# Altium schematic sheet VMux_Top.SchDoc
size A4; DocumentNumber: 1; SheetNumber: 1; SheetTotal: 5
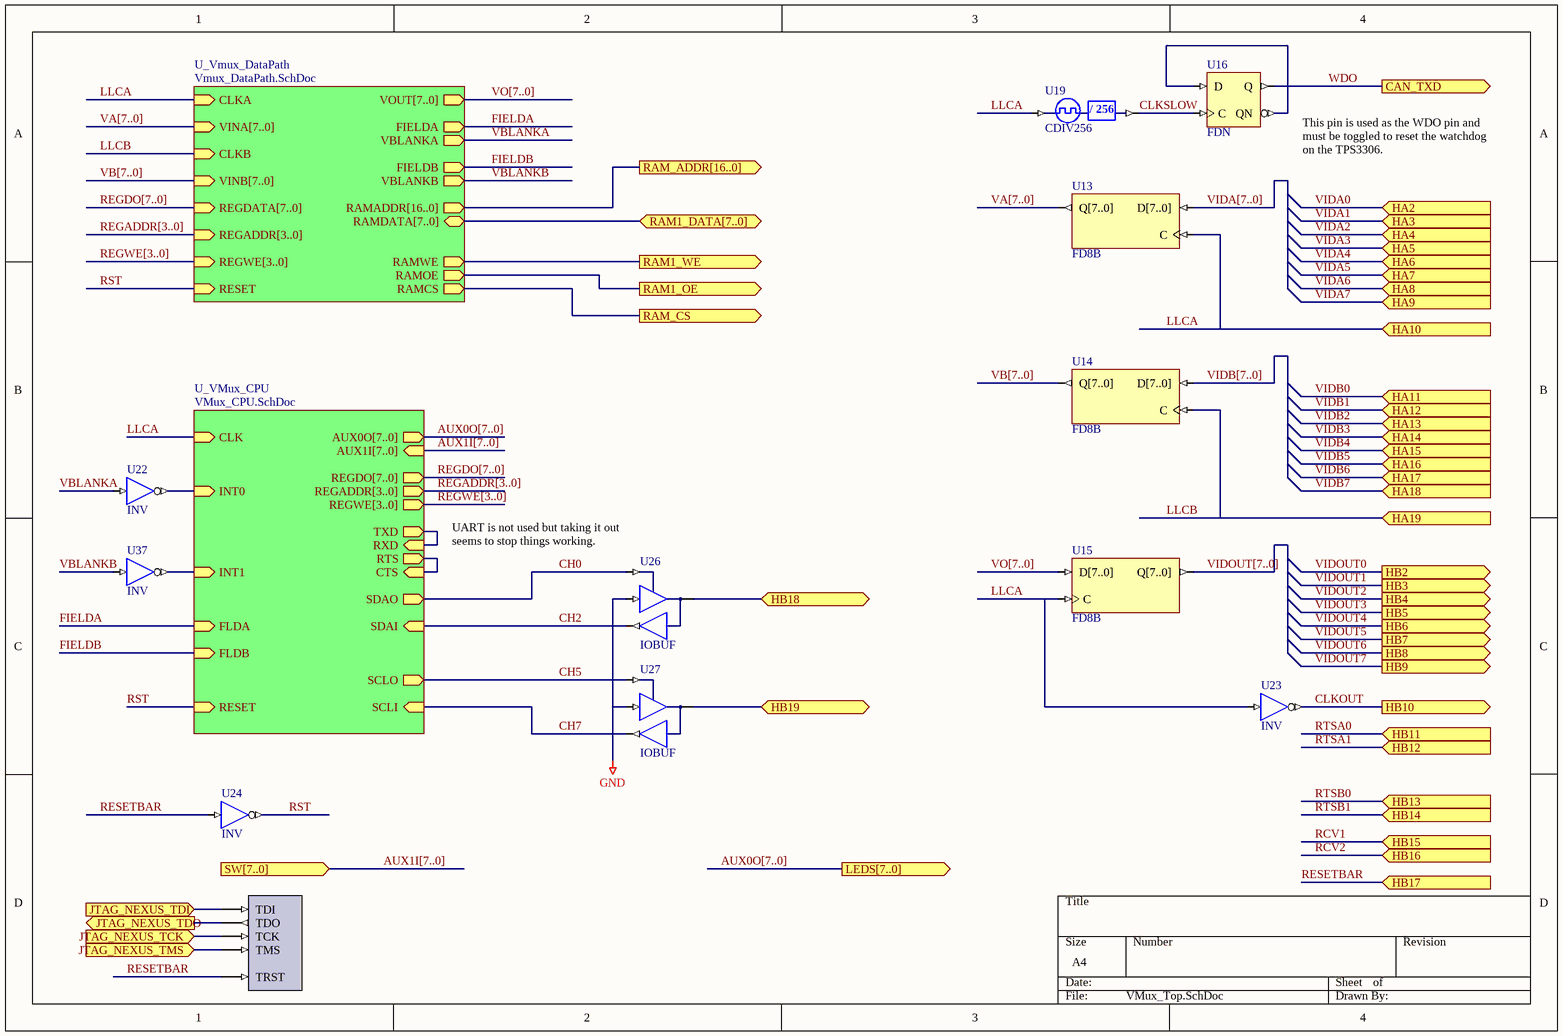
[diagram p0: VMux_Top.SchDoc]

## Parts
NEXUS_JTAG_PORT  NEXUS_JTAG_PORT  (value not drawn)
U13  FD8B
U14  FD8B
U15  FD8B
U16  FDN
U19  CDIV256
U22  INV
U23  INV
U24  INV
U26  IOBUF
U27  IOBUF
U37  INV

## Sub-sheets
U_VMux_CPU = VMux_CPU.SchDoc: CLK (in), RESET (in), SDAO (out), SCLO (out), SDAI (in), SCLI (in), AUX0O[7..0] (out), AUX1I[7..0] (in), RTS (out), TXD (out), CTS (in), RXD (in), REGDO[7..0] (out), REGADDR[3..0] (out), REGWE[3..0] (out), INT0 (in), INT1 (in), FLDA (in), FLDB (in)
U_Vmux_DataPath = Vmux_DataPath.SchDoc: REGADDR[3..0] (in), REGWE[3..0] (in), REGDATA[7..0] (in), VINA[7..0] (in), VINB[7..0] (in), CLKA (in), CLKB (in), RAMADDR[16..0] (out), RAMDATA[7..0] (bidir), RAMCS (out), RAMOE (out), RAMWE (out), VOUT[7..0] (out), RESET (in), VBLANKA (out), VBLANKB (out), FIELDA (out), FIELDB (out)

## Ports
CAN_TXD (out), HA2 (in), HA3 (in), HA4 (in), HA5 (in), HA6 (in), HA7 (in), HA8 (in), HA9 (in), HA10 (in), HA11 (in), HA12 (in), HA13 (in), HA14 (in), HA15 (in), HA16 (in), HA17 (in), HA18 (in), HA19 (in), HB2 (out), HB3 (out), HB4 (out), HB5 (out), HB6 (out), HB7 (out), HB8 (out), HB9 (out), HB10 (out), HB11 (in), HB12 (in), HB13 (in), HB14 (in), HB15 (in), HB16 (in), HB17 (in), HB18 (bidir), HB19 (bidir), JTAG_NEXUS_TCK (in), JTAG_NEXUS_TDI (in), JTAG_NEXUS_TDO (out), JTAG_NEXUS_TMS (in), LEDS[7..0] (out), RAM1_DATA[7..0] (bidir), RAM1_OE (out), RAM1_WE (out), RAM_ADDR[16..0] (out), RAM_CS (out), SW[7..0] (in)

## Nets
GND: U26.I U27.I
CH0: U26.T ; sheet U_VMux_CPU/SDAO
CH2: U26.O ; sheet U_VMux_CPU/SDAI
CH5: U27.T ; sheet U_VMux_CPU/SCLO
CH7: U27.O ; sheet U_VMux_CPU/SCLI
CLKOUT: U23.O ; port HB10
CLKSLOW: U16.C U19.CLKDV
FIELDA: sheet U_VMux_CPU/FLDA, sheet U_Vmux_DataPath/FIELDA
FIELDB: sheet U_VMux_CPU/FLDB, sheet U_Vmux_DataPath/FIELDB
HB18: U26.IO ; port HB18
HB19: U27.IO ; port HB19
JTAG_NEXUS_TCK: NEXUS_JTAG_PORT.TCK ; port JTAG_NEXUS_TCK
JTAG_NEXUS_TDI: NEXUS_JTAG_PORT.TDI ; port JTAG_NEXUS_TDI
JTAG_NEXUS_TDO: NEXUS_JTAG_PORT.TDO ; port JTAG_NEXUS_TDO
JTAG_NEXUS_TMS: NEXUS_JTAG_PORT.TMS ; port JTAG_NEXUS_TMS
LLCA: U13.C U15.C U19.CLKIN U23.I ; port HA10, sheet U_VMux_CPU/CLK, sheet U_Vmux_DataPath/CLKA
LLCB: U14.C ; port HA19, sheet U_Vmux_DataPath/CLKB
RAM1_OE: port RAM1_OE, sheet U_Vmux_DataPath/RAMOE
RAM1_WE: port RAM1_WE, sheet U_Vmux_DataPath/RAMWE
RAM_CS: port RAM_CS, sheet U_Vmux_DataPath/RAMCS
RESETBAR: NEXUS_JTAG_PORT.TRST U24.I ; port HB17
RST: U24.O ; sheet U_VMux_CPU/RESET, sheet U_Vmux_DataPath/RESET
VBLANKA: U22.I ; sheet U_Vmux_DataPath/VBLANKA
VBLANKB: U37.I ; sheet U_Vmux_DataPath/VBLANKB
WDO: U16.Q ; port CAN_TXD
NetU16_D: U16.D U16.QN
NetU22_O: U22.O ; sheet U_VMux_CPU/INT0
NetU37_O: U37.O ; sheet U_VMux_CPU/INT1
(unnamed): sheet U_VMux_CPU/RTS, sheet U_VMux_CPU/CTS
(unnamed): sheet U_VMux_CPU/TXD, sheet U_VMux_CPU/RXD  [a separate net that carries the same name]

Not connected (* = marked no-connect by the designer): U13 D[7..0] Q[7..0]; U14 D[7..0] Q[7..0]; U15 D[7..0] Q[7..0]

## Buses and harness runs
bus AUX0O[7..0] = port LEDS[7..0]
bus AUX0O[7..0] = sheet U_VMux_CPU/AUX0O[7..0]
bus AUX1I[7..0] = port SW[7..0]
bus AUX1I[7..0] = sheet U_VMux_CPU/AUX1I[7..0]
bus port RAM1_DATA[7..0] = sheet U_Vmux_DataPath/RAMDATA[7..0]
bus port RAM_ADDR[16..0] = sheet U_Vmux_DataPath/RAMADDR[16..0]
bus REGADDR[3..0] = sheet U_VMux_CPU/REGADDR[3..0]
bus REGADDR[3..0] = sheet U_Vmux_DataPath/REGADDR[3..0]
bus REGDO[7..0] = sheet U_VMux_CPU/REGDO[7..0]
bus REGDO[7..0] = sheet U_Vmux_DataPath/REGDATA[7..0]
bus REGWE[3..0] = sheet U_VMux_CPU/REGWE[3..0]
bus REGWE[3..0] = sheet U_Vmux_DataPath/REGWE[3..0]
bus VA[7..0]
bus VA[7..0] = sheet U_Vmux_DataPath/VINA[7..0]
bus VB[7..0]
bus VB[7..0] = sheet U_Vmux_DataPath/VINB[7..0]
bus VIDA[7..0]
bus VIDB[7..0]
bus VIDOUT[7..0]
bus VO[7..0]
bus VO[7..0] = sheet U_Vmux_DataPath/VOUT[7..0]

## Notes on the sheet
- (near U16) This pin is used as the WDO pin and must be toggled to reset the watchdog on the TPS3306.
- (near U26) UART is not used but taking it out seems to stop things working.

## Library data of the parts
NEXUS_JTAG_PORT = NEXUS_JTAG_PORT: Nexus Processor JTAG Chain Connector; NEXUS_JTAG_CONNECTOR: True
U13-U15 = FD8B: 8-Bit D-Type Flip-Flop, Bus Version; Xilinx Equivalent: FD8; ArchiveName: GENERIC
U16 = FDN: D-Type Flip-Flop with Inverted and Non-Inverted Outputs; ArchiveName: GENERIC
U19 = CDIV256: Clock Divider by 256; ArchiveName: GENERIC
U22 U23 U37 = INV: Inverter; ArchiveName: GENERIC
U24 = INV: Inverter; Class I: Logic Primitive; ArchiveName: GENERIC
U26 U27 = IOBUF: Input/Output Buffer; ArchiveName: GENERIC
